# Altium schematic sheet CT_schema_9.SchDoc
size 278 x 170 mm
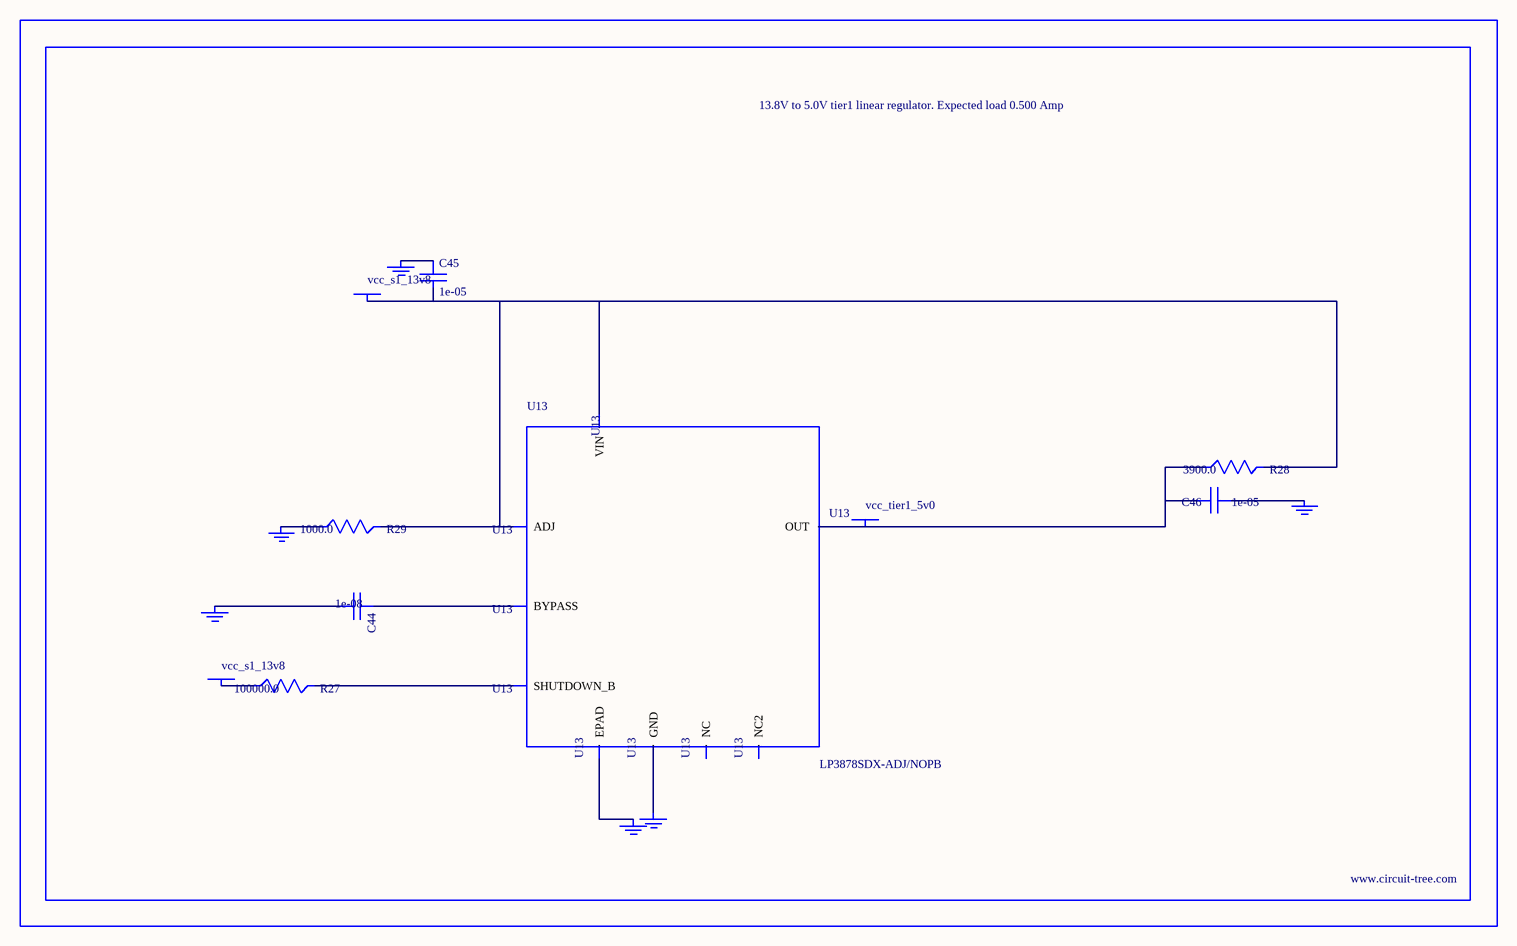
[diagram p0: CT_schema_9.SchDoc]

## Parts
BORDER8  (no value)
C44  1e-08  [C0402]
C45  1e-05  [C1210]
C46  1e-05  [C1210]
GND_INSTANCE_8_0  (no value)
GND_INSTANCE_8_1  (no value)
GND_INSTANCE_8_2  (no value)
GND_INSTANCE_8_3  (no value)
GND_INSTANCE_8_4  (no value)
GND_INSTANCE_8_5  (no value)
POWER_INSTANCE_8_0  vcc_s1_13v8
POWER_INSTANCE_8_1  vcc_s1_13v8
POWER_INSTANCE_8_2  vcc_tier1_5v0
R27  100000.0  [R0603]
R28  3900.0  [R0603]
R29  1000.0  [R0603]
U13  LP3878SDX-ADJ/NOPB  [WSON-8]

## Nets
NetC44_1: C44.1 U13.1(BYPASS)
NetC44_2: C44.2 GND_INSTANCE_8_0.0(GND)
NetC45_1: C45.1 GND_INSTANCE_8_1.0(GND)
NetC45_2: C45.2 POWER_INSTANCE_8_0.0(PWR) R28.2 R29.2 U13.4(VIN) U13.6(ADJ)
NetC46_1: C46.1 GND_INSTANCE_8_2.0(GND)
NetC46_2: C46.2 POWER_INSTANCE_8_2.0(PWR) R28.1 U13.5(OUT)
NetGND_INSTANCE_8_3_0: GND_INSTANCE_8_3.0(GND) R29.1
NetGND_INSTANCE_8_4_0: GND_INSTANCE_8_4.0(GND) U13.PAD(EPAD)
NetGND_INSTANCE_8_5_0: GND_INSTANCE_8_5.0(GND) U13.3(GND)
NetPOWER_INSTANCE_8_1_0: POWER_INSTANCE_8_1.0(PWR) R27.1
NetR27_2: R27.2 U13.8(SHUTDOWN_B)

Not connected (* = marked no-connect by the designer): U13 2(NC) 7(NC2)

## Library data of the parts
BORDER8 = BORDER_PAGE8
C44 = C0402C103K3RAC
C45 = C1210C106K5PACTU
C46 = GRM32DR61E106MA12L
GND_INSTANCE_8_0-GND_INSTANCE_8_5 = GND
POWER_INSTANCE_8_0-POWER_INSTANCE_8_2 = PWR
R27 = RC0603JR-07100KL
R28 = RC0603JR-073K9L
R29 = RC0603JR-071KL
